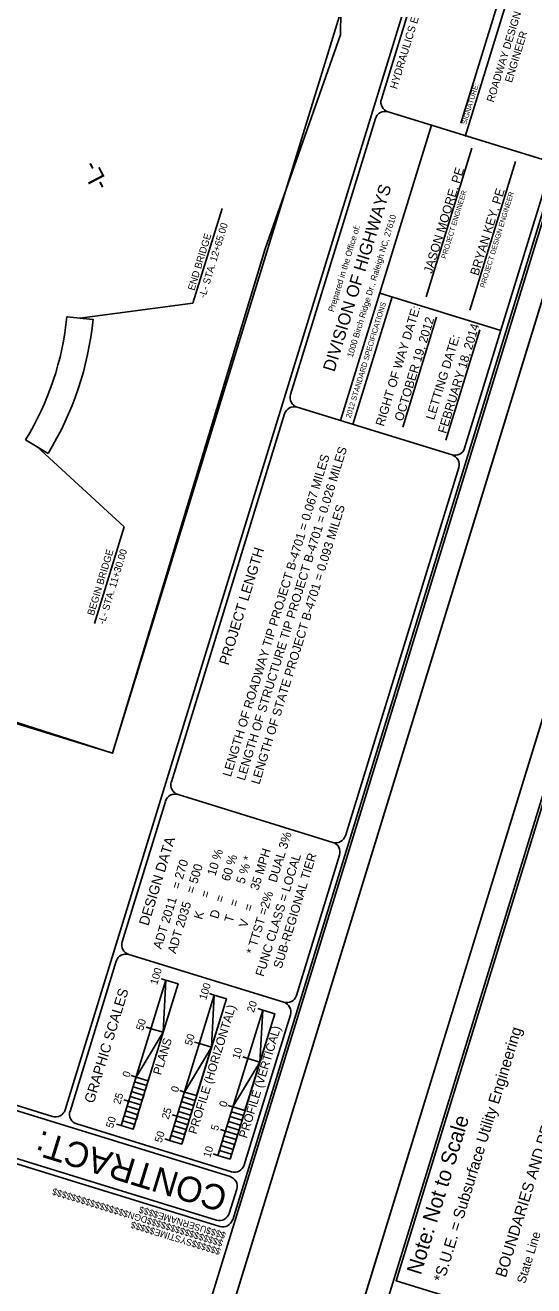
# Model space of a CAD drawing. Extents: x 1347947 to 1350662, y 1027710 to 1030532.
# Drawn here: x 1348821 to 1349324, y 1028346 to 1029589 of the extents above; entities that cross this region are included whole.
import ezdxf

# ---------------------------------------------------------------- set-up
doc = ezdxf.new("R2010")
doc.units = 0
for name, color, linetype in [('Prop Leader Line Light', 7, 'Continuous'), ('Prop Leader Line Medium', 7, 'Continuous'), ('Prop Shade Medium', 7, 'Continuous'), ('Sheet Clip Boundary CELL', 7, 'Continuous'), ('Sheet Cutting Line CELL', 7, 'Continuous'), ('Sheet Data Field CELL', 7, 'Continuous'), ('Sheet Plot Border Inside CELL', 7, 'Continuous'), ('Sheet Plot Border Outside CELL', 7, 'Continuous'), ('Sheet Symbology CELL', 7, 'Continuous'), ('Sheet Title CELL', 7, 'Continuous')]:
    doc.layers.add(name, color=color, linetype=linetype)

msp = doc.modelspace()

# ---------------------------------------------------------------- linework, layer by layer
at = {"layer": 'Prop Leader Line Medium'}
for p, q in [((1348987.1, 1029315.3), (1349015.9, 1029408.7)), ((1348875.5, 1029300.5), (1348987.1, 1029315.3)), ((1348832.9, 1029173.6), (1348919.1, 1029094.6)), ((1348919.1, 1029094.6), (1348889.7, 1028999.1))]:
    msp.add_line(p, q, dxfattribs=at)
msp.add_lwpolyline([(1348456.6, 1029010.1), (1348682, 1029741.9), (1349133.1, 1029603), (1348907.7, 1028871.1)], close=True, dxfattribs=at)
at = {"layer": 'Prop Shade Medium'}
for p, q in [((1348862.6, 1029301.8), (1348863.1, 1029301.8)), ((1348862.6, 1029301.8), (1348888.4, 1029299.2)), ((1348844, 1029166.8), (1348821.8, 1029180.4))]:
    msp.add_line(p, q, dxfattribs=at)
for radius in [287, 313]:
    msp.add_arc((1348577, 1029330.2), radius, 328.5401, 354.3232, dxfattribs=at)
at = {"layer": 'Sheet Clip Boundary CELL'}
msp.add_lwpolyline([(1348456.6, 1029010.1), (1348582.5, 1029132.6), (1348611.5, 1029255.1), (1348756.6, 1029710.8), (1349133.1, 1029603), (1349132.8, 1029579.9), (1349058.5, 1029368.8), (1348907.7, 1028871.1), (1348666.1, 1028948.4)], close=True, dxfattribs=at)
at = {"layer": 'Sheet Cutting Line CELL'}
msp.add_line((1348998.1, 1028234.2), (1349493.8, 1029843.6), dxfattribs=at)
at = {"layer": 'Sheet Data Field CELL'}
for p, q in [((1348960.4, 1028647.1), (1348955.6, 1028648.6)), ((1348945.7, 1028599.4), (1348940.9, 1028600.8)), ((1348923.6, 1028527.7), (1348918.8, 1028529.1)), ((1348916.2, 1028503.8), (1348911.5, 1028505.2)), ((1349023.4, 1028401.2), (1349023.4, 1028401.2))]:
    msp.add_line(p, q, dxfattribs=at)
at = {"layer": 'Sheet Plot Border Inside CELL'}
msp.add_lwpolyline([(1348980.5, 1028253.2), (1349471, 1029845.9), (1348462.6, 1030156.5), (1347972.2, 1028563.8)], close=True, dxfattribs=at)
at = {"layer": 'Sheet Plot Border Outside CELL'}
msp.add_lwpolyline([(1348442.5, 1030167.4), (1347946.9, 1028558), (1348998.1, 1028234.2), (1349493.8, 1029843.6)], close=True, dxfattribs=at)
at = {"layer": 'Sheet Symbology CELL'}
msp.add_line((1349610.3, 1029807.7), (1349114.7, 1028198.3), dxfattribs=at)
for points in [[(1350166, 1027874.5), (1350661.6, 1029484), (1349610.3, 1029807.7), (1349114.7, 1028198.3)], [(1350148.3, 1027893.6), (1350638.8, 1029486.3), (1349630.5, 1029796.8), (1349140, 1028204.1)], [(1349629.2, 1029784.1), (1349187.7, 1028350.5), (1350190.3, 1028041.8), (1350631.7, 1029475.4)]]:
    msp.add_lwpolyline(points, close=True, dxfattribs=at)
at = {"layer": 'Sheet Title CELL'}
for p, q in [((1348860.9, 1028519.2), (1349278.9, 1029876.3)), ((1349173.3, 1029516.5), (1349232.1, 1029707.4)), ((1349256.1, 1029479.6), (1349321, 1029690.5)), ((1349251.8, 1029492.8), (1349294.2, 1029630.7)), ((1349083.5, 1029225), (1349167.4, 1029497.4)), ((1349332.8, 1029456.9), (1349179.9, 1029504)), ((1349222.7, 1029490.8), (1349132.9, 1029199.3)), ((1349217.6, 1029321.3), (1349262.7, 1029468)), ((1349260.6, 1029308.1), (1349305.7, 1029454.8)), ((1349171.6, 1029325), (1349291.3, 1029288.2)), ((1349183.8, 1029321.3), (1349145.1, 1029195.6)), ((1349227.8, 1029301.5), (1349194.3, 1029192.7)), ((1349270.5, 1029288.7), (1349237, 1029180)), ((1349172.7, 1029285.1), (1349172.7, 1029285.1)), ((1349211, 1029247.1), (1349211, 1029247.1)), ((1349090.1, 1029212.5), (1349243, 1029165.4)), ((1348965.8, 1028842.7), (1349077.6, 1029205.9)), ((1348972.4, 1028830.2), (1349125.3, 1028783.1)), ((1348917.2, 1028685), (1348959.9, 1028823.6)), ((1349023.8, 1028453.4), (1348049, 1028753.6)), ((1348848.4, 1028512.6), (1348050.4, 1028758.4)), ((1348865.7, 1028517.7), (1348911.3, 1028665.9)), ((1348923.8, 1028672.5), (1349076.8, 1028625.4)), ((1348960.4, 1028647.1), (1348916.2, 1028503.8)), ((1348928.2, 1028500.1), (1348972.4, 1028643.4)), ((1348960.4, 1028647.1), (1348955.6, 1028648.6)), ((1348972.4, 1028643.4), (1348960.4, 1028647.1)), ((1349008.2, 1028632.4), (1348964, 1028489)), ((1349008.2, 1028632.4), (1348964, 1028489)), ((1348976, 1028485.4), (1349020.1, 1028628.7)), ((1349008.2, 1028632.4), (1349003.4, 1028633.9)), ((1349008.2, 1028632.4), (1349003.4, 1028633.9)), ((1349020.1, 1028628.7), (1349008.2, 1028632.4)), ((1349056, 1028617.7), (1349011.8, 1028474.3)), ((1349056, 1028617.7), (1349011.8, 1028474.3)), ((1349056, 1028617.7), (1349011.8, 1028474.3)), ((1349056, 1028617.7), (1349051.2, 1028619.2)), ((1349056, 1028617.7), (1349051.2, 1028619.2)), ((1349056, 1028617.7), (1349051.2, 1028619.2)), ((1349067.9, 1028614), (1349056, 1028617.7)), ((1349023.8, 1028470.7), (1349067.9, 1028614)), ((1348945.7, 1028599.3), (1348940.9, 1028600.8)), ((1348945.7, 1028599.3), (1348957.6, 1028595.7)), ((1348993.5, 1028584.6), (1348988.7, 1028586.1)), ((1348993.5, 1028584.6), (1348988.7, 1028586.1)), ((1348993.5, 1028584.6), (1349005.4, 1028580.9)), ((1349041.3, 1028569.9), (1349036.5, 1028571.4)), ((1349041.3, 1028569.9), (1349036.5, 1028571.4)), ((1349041.3, 1028569.9), (1349036.5, 1028571.4)), ((1349041.3, 1028569.9), (1349053.2, 1028566.2)), ((1348931, 1028551.5), (1348926.2, 1028553)), ((1348923.6, 1028527.7), (1348918.8, 1028529.1)), ((1348926.5, 1028537.2), (1348938.5, 1028533.5)), ((1348978.7, 1028536.8), (1348974, 1028538.3)), ((1348978.7, 1028536.8), (1348974, 1028538.3)), ((1348974.3, 1028522.5), (1348986.3, 1028518.8)), ((1349026.5, 1028522.1), (1349021.8, 1028523.6)), ((1349026.5, 1028522.1), (1349021.8, 1028523.6)), ((1349026.5, 1028522.1), (1349021.8, 1028523.6)), ((1349025.3, 1028458.2), (1348872.3, 1028505.3)), ((1348916.2, 1028503.8), (1348911.5, 1028505.2)), ((1348911.5, 1028505.2), (1348911.5, 1028505.2)), ((1348916.2, 1028503.8), (1348928.2, 1028500.1)), ((1348916.2, 1028503.8), (1348916.2, 1028503.8)), ((1348971.4, 1028512.9), (1348966.6, 1028514.4)), ((1348971.4, 1028512.9), (1348966.6, 1028514.4)), ((1349022.1, 1028507.8), (1349034.1, 1028504.1)), ((1348964, 1028489), (1348959.3, 1028490.5)), ((1348964, 1028489), (1348959.3, 1028490.5)), ((1348959.3, 1028490.5), (1348959.3, 1028490.5)), ((1349019.2, 1028498.2), (1349014.4, 1028499.7)), ((1349019.2, 1028498.2), (1349014.4, 1028499.7)), ((1349019.2, 1028498.2), (1349014.4, 1028499.7)), ((1348964, 1028489), (1348976, 1028485.4)), ((1348964, 1028489), (1348964, 1028489)), ((1348964, 1028489), (1348964, 1028489)), ((1349011.8, 1028474.3), (1349007, 1028475.8)), ((1349011.8, 1028474.3), (1349007, 1028475.8)), ((1349011.8, 1028474.3), (1349007, 1028475.8)), ((1349007, 1028475.8), (1349007, 1028475.8)), ((1349011.8, 1028474.3), (1349023.8, 1028470.7)), ((1349011.8, 1028474.3), (1349011.8, 1028474.3)), ((1349011.8, 1028474.3), (1349011.8, 1028474.3)), ((1349011.8, 1028474.3), (1349011.8, 1028474.3)), ((1349023.4, 1028401.2), (1349023.4, 1028401.2)), ((1349023.4, 1028401.2), (1349023.4, 1028401.2)), ((1349023.4, 1028401.2), (1349023.4, 1028401.2)), ((1349023.4, 1028401.2), (1349023.4, 1028401.2))]:
    msp.add_line(p, q, dxfattribs=at)
for points in [[(1349026.4, 1028410.7), (1349461.9, 1029825.2)], [(1349255.5, 1029172), (1349339.4, 1029444.4)], [(1349137.8, 1028789.7), (1349249.7, 1029152.9)], [(1349089.3, 1028632), (1349131.9, 1028770.6)], [(1348029.5, 1028707.3), (1349013.8, 1028404.1)], [(1348029.5, 1028707.3), (1349013.8, 1028404.1)], [(1348035.7, 1028710.6), (1349010.5, 1028410.4)], [(1349037.8, 1028464.8), (1349083.4, 1028612.9)], [(1349023, 1028417), (1349030.4, 1028440.9)]]:
    msp.add_lwpolyline(points, dxfattribs=at)
for points in [[(1348960.4, 1028647.1), (1348957.6, 1028595.7), (1348972.4, 1028643.4)], [(1349008.2, 1028632.4), (1349005.4, 1028580.9), (1349020.1, 1028628.7)], [(1349056, 1028617.7), (1349053.2, 1028566.2), (1349067.9, 1028614)], [(1348931, 1028551.5), (1348957.6, 1028595.7), (1348942.9, 1028547.9)], [(1348978.7, 1028536.8), (1349005.4, 1028580.9), (1348990.7, 1028533.2)], [(1349026.5, 1028522.1), (1349053.2, 1028566.2), (1349038.5, 1028518.4)], [(1348928, 1028542), (1348929.5, 1028546.8), (1348941.4, 1028543.1), (1348940, 1028538.3)], [(1348922.1, 1028522.9), (1348923.6, 1028527.7), (1348935.6, 1028524), (1348934.1, 1028519.2)], [(1348925.1, 1028532.4), (1348926.5, 1028537.2), (1348938.5, 1028533.5), (1348937, 1028528.8)], [(1348975.8, 1028527.3), (1348977.3, 1028532.1), (1348989.2, 1028528.4), (1348987.8, 1028523.6)], [(1348919.2, 1028513.3), (1348920.7, 1028518.1), (1348932.6, 1028514.4), (1348931.2, 1028509.7)], [(1348972.9, 1028517.7), (1348974.3, 1028522.5), (1348986.3, 1028518.8), (1348984.8, 1028514)], [(1349023.6, 1028512.6), (1349025.1, 1028517.3), (1349037, 1028513.7), (1349035.5, 1028508.9)], [(1348916.2, 1028503.8), (1348917.7, 1028508.5), (1348929.7, 1028504.9), (1348928.2, 1028500.1)], [(1348967, 1028498.6), (1348968.4, 1028503.4), (1348980.4, 1028499.7), (1348978.9, 1028494.9)], [(1348969.9, 1028508.2), (1348971.4, 1028512.9), (1348983.3, 1028509.3), (1348981.9, 1028504.5)], [(1349020.7, 1028503), (1349022.1, 1028507.8), (1349034.1, 1028504.1), (1349032.6, 1028499.3)], [(1348964, 1028489), (1348965.5, 1028493.8), (1348977.4, 1028490.1), (1348976, 1028485.4)], [(1349017.7, 1028493.4), (1349019.2, 1028498.2), (1349031.1, 1028494.5), (1349029.7, 1028489.8)], [(1349011.8, 1028474.3), (1349013.3, 1028479.1), (1349025.2, 1028475.4), (1349023.8, 1028470.7)], [(1349014.8, 1028483.9), (1349016.2, 1028488.7), (1349028.2, 1028485), (1349026.7, 1028480.2)]]:
    msp.add_lwpolyline(points, close=True, dxfattribs=at)
for centre, start, end in [((1349182.8, 1029513.5), 162.8834, 252.8834), ((1349176.9, 1029494.4), 72.8834, 162.8834), ((1349093, 1029222.1), 162.8834, 252.8834), ((1349087.1, 1029202.9), 72.8834, 162.8834), ((1349245.9, 1029175), 252.8834, 342.8834), ((1349240.1, 1029155.8), 342.8834, 72.8834), ((1348975.3, 1028839.8), 162.8834, 252.8834), ((1348969.4, 1028820.7), 72.8834, 162.8834), ((1349128.2, 1028792.7), 252.8834, 342.8834), ((1349122.3, 1028773.6), 342.8834, 72.8834), ((1348926.7, 1028682.1), 162.8834, 252.8834), ((1348920.9, 1028663), 72.8834, 162.8834), ((1349079.7, 1028635), 252.8834, 342.8834), ((1349073.8, 1028615.9), 342.8834, 72.8834), ((1348851.3, 1028522.2), 252.8834, 342.8834), ((1348875.2, 1028514.8), 162.8834, 252.8834), ((1349020.8, 1028443.8), 342.8834, 72.8834), ((1349028.2, 1028467.7), 252.8834, 342.8834), ((1349013.4, 1028420), 252.8834, 342.8834), ((1349016.7, 1028413.7), 252.8834, 342.8834)]:
    msp.add_arc(centre, 10, start, end, dxfattribs=at)

# ---------------------------------------------------------------- texts
at = {"layer": 'Prop Leader Line Light'}
for s, p in [('-L- STA. 12+65.00', (1348999.3, 1029319.7)), ('BEGIN BRIDGE', (1348889.1, 1029006.4)), ('-L- STA. 11+30.00', (1348899.8, 1028997.8))]:
    msp.add_text(s, height=7, rotation=73.074, dxfattribs=at).set_placement(p)
at = {"layer": 'Prop Leader Line Medium'}
msp.add_text('END BRIDGE', height=7, rotation=73.074, dxfattribs=at).set_placement((1348988.5, 1029327.1))
at = {"layer": 'Sheet Data Field CELL'}
for s, height, rotation, p in [('-L-', 17.5, 117.8921, (1348904.4, 1029431.9)), ('JASON MOORE, PE', 8.75, 72.8834, (1349223.1, 1029343.7)), ('BRYAN KEY, PE', 8.75, 72.8834, (1349269, 1029341.7)), ('OCTOBER 19, 2012', 8.75, 72.8834, (1349194.2, 1029198)), ('FEBRUARY 18, 2014', 8.75, 72.8834, (1349237.1, 1029185.9)), ('LENGTH OF ROADWAY TIP PROJECT B-4701 = 0.067 MILES', 8.75, 72.8834, (1349024.5, 1028847.2)), ('LENGTH OF STRUCTURE TIP PROJECT B-4701 = 0.026 MILES', 8.75, 72.8834, (1349038.3, 1028843.5)), ('LENGTH OF STATE PROJECT B-4701 = 0.093 MILES', 8.75, 72.8834, (1349052.7, 1028839.7)), ('DUAL 3%', 8.75, 72.8834, (1349069.6, 1028742.9)), ('35 MPH', 8.75, 72.8834, (1349051.7, 1028735.2)), ('= 270', 8.75, 72.8834, (1348974, 1028736.4)), ('10 %', 8.75, 72.8834, (1349009.2, 1028749.4)), ('60 %', 8.75, 72.8834, (1349023.2, 1028744.1)), ('5 % *', 8.75, 72.8834, (1349037.8, 1028741.5)), ('FUNC CLASS = LOCAL', 8.75, 72.8834, (1349056.9, 1028650.1)), ('SUB-REGIONAL TIER', 8.75, 72.8834, (1349074.6, 1028658)), ('= 500', 8.75, 72.8834, (1348988.3, 1028732)), ('ADT 2011', 8.75, 72.8834, (1348955.8, 1028677.2)), ('=', 8.75, 72.8834, (1349002.5, 1028727.6)), ('=', 8.75, 72.8834, (1349016.9, 1028723.2)), ('=', 8.75, 72.8834, (1349030.8, 1028718.9)), ('* TTST =2%', 8.75, 72.8834, (1349047.8, 1028672.1)), ('ADT 2035', 8.75, 72.8834, (1348970.1, 1028672.8)), (' K', 8.75, 72.8834, (1348995.1, 1028703.3)), ('D', 8.75, 72.8834, (1349011.8, 1028707.1)), ('=', 8.75, 72.8834, (1349045.2, 1028714.5)), ('T', 8.75, 72.8834, (1349026.2, 1028703.3)), ('V', 8.75, 72.8834, (1349040.3, 1028698.3)), ('100', 7.5, 72.8834, (1348951.7, 1028642)), ('100', 7.5, 72.8834, (1349000.1, 1028627.1)), ('20', 7.5, 72.8834, (1349047.3, 1028614.7)), ('50', 7.5, 72.8834, (1348937.7, 1028596.9)), ('50', 7.5, 72.8834, (1348985.8, 1028582.1)), ('10', 7.5, 72.8834, (1349032.8, 1028568.6)), ('25', 7.5, 72.8834, (1348915.2, 1028524)), ('25', 7.5, 72.8834, (1348963, 1028509.3)), ('50', 7.5, 72.8834, (1348908, 1028500.6)), ('5', 7.5, 72.8834, (1349011.6, 1028498)), ('50', 7.5, 72.8834, (1348956.1, 1028486.2)), ('10', 7.5, 72.8834, (1349004.1, 1028471.4))]:
    msp.add_text(s, height=height, rotation=rotation, dxfattribs=at).set_placement(p)
at = {"layer": 'Sheet Symbology CELL'}
for s, height, p in [('*S.U.E. = Subsurface Utility Engineering', 11, (1349235, 1028348.6)), ('BOUNDARIES AND PROPERTY:', 11, (1349296.1, 1028353)), ('Note: Not to Scale', 15, (1349212.2, 1028355.6)), ('State Line', 8.75, (1349315.2, 1028347.1))]:
    msp.add_text(s, height=height, rotation=72.8834, dxfattribs=at).set_placement(p)
at = {"layer": 'Sheet Title CELL'}
for s, height, rotation, p in [(' HYDRAULICS ENGINEER', 7.5, 72.8834, (1349187.7, 1029523.2)), ('ROADWAY DESIGN', 7.499, 72.8834, (1349284.1, 1029512.8)), ('ENGINEER', 7.5, 72.8834, (1349302.1, 1029532.2)), ('SIGNATURE:', 5, 72.8834, (1349257.1, 1029490.9)), ('DIVISION OF HIGHWAYS', 12.187, 72.8834, (1349126.8, 1029246.7)), ('PROJECT ENGINEER', 5, 72.8834, (1349236.9, 1029358.6)), ('PROJECT DESIGN ENGINEER', 5, 72.8834, (1349275.2, 1029330)), ('1000 Birch Ridge Dr., Raleigh NC, 27610', 6, 72.8834, (1349144.8, 1029261.2)), ('Prepared in the Office of:', 5.999, 72.8834, (1349126.2, 1029306)), ('2012 STANDARD SPECIFICATIONS', 5.2, 72.8834, (1349142.8, 1029201.3)), ('RIGHT OF WAY DATE: ', 8.75, 72.8834, (1349175.6, 1029193)), ('LETTING DATE:', 8.75, 72.8834, (1349225.3, 1029199.3)), ('PROJECT LENGTH', 10, 72.8834, (1349022.2, 1028957.3)), ('DESIGN DATA', 10, 72.8834, (1348943, 1028700.2)), ('GRAPHIC SCALES', 10, 72.8834, (1348889.1, 1028525)), ('PROFILE (HORIZONTAL)', 8.5, 72.8834, (1348990.5, 1028494.6)), ('PLANS', 8.5, 72.8834, (1348955.5, 1028552.9)), ('PROFILE (VERTICAL)', 8.5, 72.8834, (1349040.3, 1028490.6)), ('0', 7.5, 72.8834, (1348924.3, 1028550.7)), ('0', 7.5, 72.8834, (1348972.1, 1028536)), ('0', 7.5, 72.8834, (1348972.2, 1028536)), ('0', 7.5, 72.8834, (1349019.8, 1028521.3)), ('0', 7.5, 72.8834, (1349020, 1028521.3)), ('0', 7.5, 72.8834, (1349020, 1028521.3)), ('CONTRACT:', 25, 162.8834, (1349022.9, 1028441.8)), ('$$$$$$$$$$$$$$$$DGN$$$$$$$$$$$$$$$$', 6.563, 162.8834, (1349017.4, 1028390.3)), ('$$$$USERNAME$$$$', 6.563, 162.8834, (1349020, 1028398)), ('$$$$$$SYSTIME$$$$$', 6.563, 162.8834, (1349015.1, 1028382.1))]:
    msp.add_text(s, height=height, rotation=rotation, dxfattribs=at).set_placement(p)

doc.saveas('drawing.dxf')
